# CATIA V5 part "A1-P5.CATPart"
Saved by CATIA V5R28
Part number: Part5
Source: Unknown
Bounding box of the stored display mesh (mm): x -9.96 to 9.96, y -9.96 to 9.96, z 0 to 40
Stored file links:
  E:\TP Catia - Documents\Additional Exercise\Contrôle\Problem-3-Section-J\A1-P5.CATPart
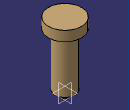
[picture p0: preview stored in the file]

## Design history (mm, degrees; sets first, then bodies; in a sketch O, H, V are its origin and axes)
Body1 (main body)
  Solid1 "Corps principal": solid without history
